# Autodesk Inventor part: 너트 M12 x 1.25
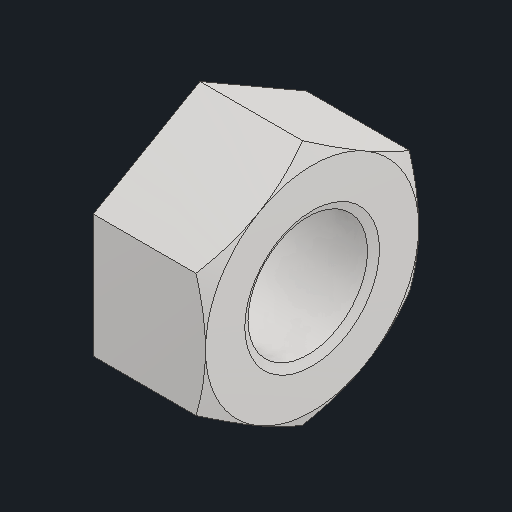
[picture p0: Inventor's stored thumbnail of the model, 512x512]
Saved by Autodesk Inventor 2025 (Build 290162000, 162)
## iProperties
Created: 2025-08
Part Number: 너트 M12 x 1.25
Material: 스테인리스강
Description: 6각 너트
Document SubType Name: Modeling
Designer: infra14
Density: 8.08 g/cm^3
Appearance: 기본값
Author: jhkim
Sending System: Autodesk Inventor 2026
Preprocessor: ST-DEVELOPER v20.1
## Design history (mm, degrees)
feature "Solid1"
node "솔리드1"
